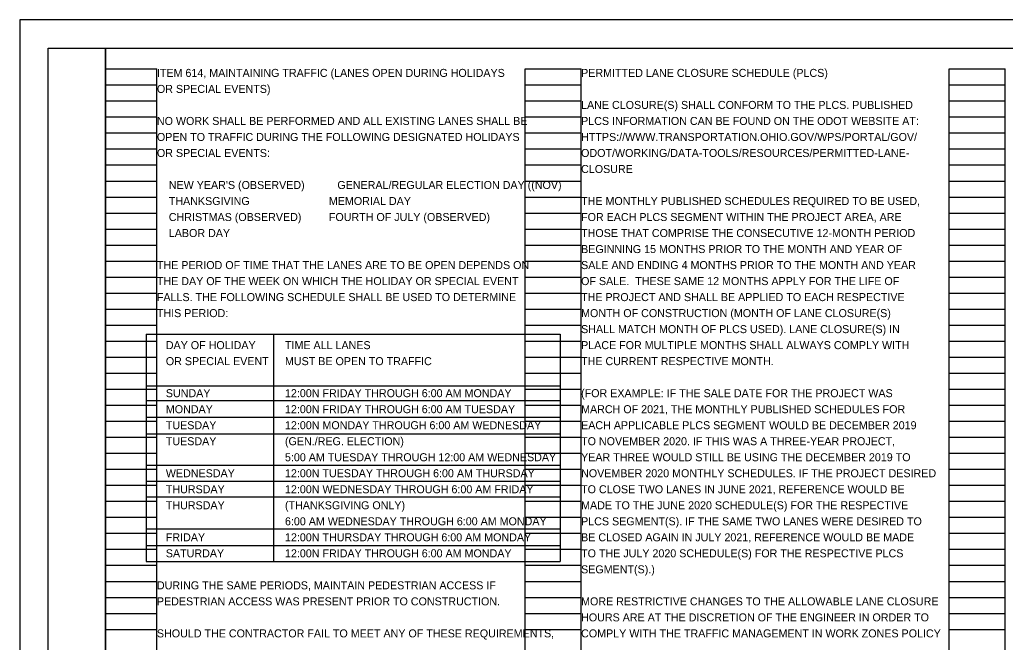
# Model space of a CAD drawing. Extents: x 0 to 49.3, y -31.9 to 22.
# Drawn here: x 0 to 17.24, y 11.11 to 22 of the extents above; entities that cross this region are included whole.
import ezdxf

# ---------------------------------------------------------------- set-up
doc = ezdxf.new("R2010")
doc.units = 0
for name, color, linetype in [('SH_Border', 7, 'Continuous'), ('SH_Cut_Line', 7, 'Continuous'), ('SH_Data', 7, 'Continuous'), ('SH_Text', 7, 'Continuous')]:
    doc.layers.add(name, color=color, linetype=linetype)

msp = doc.modelspace()

# ---------------------------------------------------------------- linework, layer by layer
at = {"layer": 'SH_Border'}
for points in [[(0.5, 21.5), (1.5, 21.5), (1.5, 0.5), (0.5, 0.5)], [(1.5, 21.5), (33.5, 21.5), (33.5, 0.5), (1.5, 0.5)]]:
    msp.add_lwpolyline(points, close=True, dxfattribs=at)
at = {"layer": 'SH_Cut_Line'}
msp.add_lwpolyline([(0, 0), (34, 0), (34, 22), (0, 22)], close=True, dxfattribs=at)
at = {"layer": 'SH_Data'}
for p, q in [((1.5, 0.98), (1.5, 21.14)), ((1.5, 21.14), (2.4, 21.14)), ((2.4, 0.98), (2.4, 21.14)), ((8.84, 0.98), (8.84, 21.14)), ((8.84, 21.14), (9.82, 21.14)), ((9.82, 0.98), (9.82, 21.14)), ((16.26, 0.98), (16.26, 21.14)), ((16.26, 21.14), (17.24, 21.14)), ((17.24, 0.98), (17.24, 21.14)), ((1.5, 20.86), (2.4, 20.86)), ((8.84, 20.86), (9.82, 20.86)), ((16.26, 20.86), (17.24, 20.86)), ((1.5, 20.58), (2.4, 20.58)), ((8.84, 20.58), (9.82, 20.58)), ((16.26, 20.58), (17.24, 20.58)), ((1.5, 20.3), (2.4, 20.3)), ((8.84, 20.3), (9.82, 20.3)), ((16.26, 20.3), (17.24, 20.3)), ((1.5, 20.02), (2.4, 20.02)), ((8.84, 20.02), (9.82, 20.02)), ((16.26, 20.02), (17.24, 20.02)), ((1.5, 19.74), (2.4, 19.74)), ((8.84, 19.74), (9.82, 19.74)), ((16.26, 19.74), (17.24, 19.74)), ((1.5, 19.46), (2.4, 19.46)), ((8.84, 19.46), (9.82, 19.46)), ((16.26, 19.46), (17.24, 19.46)), ((1.5, 19.18), (2.4, 19.18)), ((8.84, 19.18), (9.82, 19.18)), ((16.26, 19.18), (17.24, 19.18)), ((1.5, 18.9), (2.4, 18.9)), ((8.84, 18.9), (9.82, 18.9)), ((16.26, 18.9), (17.24, 18.9)), ((1.5, 18.62), (2.4, 18.62)), ((8.84, 18.62), (9.82, 18.62)), ((16.26, 18.62), (17.24, 18.62)), ((1.5, 18.34), (2.4, 18.34)), ((8.84, 18.34), (9.82, 18.34)), ((16.26, 18.34), (17.24, 18.34)), ((1.5, 18.06), (2.4, 18.06)), ((8.84, 18.06), (9.82, 18.06)), ((16.26, 18.06), (17.24, 18.06)), ((1.5, 17.78), (2.4, 17.78)), ((8.84, 17.78), (9.82, 17.78)), ((16.26, 17.78), (17.24, 17.78)), ((1.5, 17.5), (2.4, 17.5)), ((8.84, 17.5), (9.82, 17.5)), ((16.26, 17.5), (17.24, 17.5)), ((1.5, 17.22), (2.4, 17.22)), ((8.84, 17.22), (9.82, 17.22)), ((16.26, 17.22), (17.24, 17.22)), ((1.5, 16.94), (2.4, 16.94)), ((8.84, 16.94), (9.82, 16.94)), ((16.26, 16.94), (17.24, 16.94)), ((1.5, 16.66), (2.4, 16.66)), ((8.84, 16.66), (9.82, 16.66)), ((16.26, 16.66), (17.24, 16.66)), ((1.5, 16.38), (2.4, 16.38)), ((8.84, 16.38), (9.82, 16.38)), ((16.26, 16.38), (17.24, 16.38)), ((1.5, 16.1), (2.4, 16.1)), ((8.84, 16.1), (9.82, 16.1)), ((16.26, 16.1), (17.24, 16.1)), ((1.5, 15.82), (2.4, 15.82)), ((8.84, 15.82), (9.82, 15.82)), ((16.26, 15.82), (17.24, 15.82)), ((1.5, 15.54), (2.4, 15.54)), ((8.84, 15.54), (9.82, 15.54)), ((16.26, 15.54), (17.24, 15.54)), ((1.5, 15.26), (2.4, 15.26)), ((8.84, 15.26), (9.82, 15.26)), ((16.26, 15.26), (17.24, 15.26)), ((1.5, 14.98), (2.4, 14.98)), ((8.84, 14.98), (9.82, 14.98)), ((16.26, 14.98), (17.24, 14.98)), ((1.5, 14.7), (2.4, 14.7)), ((8.84, 14.7), (9.82, 14.7)), ((16.26, 14.7), (17.24, 14.7)), ((1.5, 14.42), (2.4, 14.42)), ((8.84, 14.42), (9.82, 14.42)), ((16.26, 14.42), (17.24, 14.42)), ((1.5, 14.14), (2.4, 14.14)), ((8.84, 14.14), (9.82, 14.14)), ((16.26, 14.14), (17.24, 14.14)), ((1.5, 13.86), (2.4, 13.86)), ((8.84, 13.86), (9.82, 13.86)), ((16.26, 13.86), (17.24, 13.86)), ((1.5, 13.58), (2.4, 13.58)), ((8.84, 13.58), (9.82, 13.58)), ((16.26, 13.58), (17.24, 13.58)), ((1.5, 13.3), (2.4, 13.3)), ((8.84, 13.3), (9.82, 13.3)), ((16.26, 13.3), (17.24, 13.3)), ((1.5, 13.02), (2.4, 13.02)), ((8.84, 13.02), (9.82, 13.02)), ((16.26, 13.02), (17.24, 13.02)), ((1.5, 12.74), (2.4, 12.74)), ((8.84, 12.74), (9.82, 12.74)), ((16.26, 12.74), (17.24, 12.74)), ((1.5, 12.46), (2.4, 12.46)), ((8.84, 12.46), (9.82, 12.46)), ((16.26, 12.46), (17.24, 12.46)), ((1.5, 12.18), (2.4, 12.18)), ((8.84, 12.18), (9.82, 12.18)), ((16.26, 12.18), (17.24, 12.18)), ((1.5, 11.9), (2.4, 11.9)), ((8.84, 11.9), (9.82, 11.9)), ((16.26, 11.9), (17.24, 11.9)), ((1.5, 11.62), (2.4, 11.62)), ((8.84, 11.62), (9.82, 11.62)), ((16.26, 11.62), (17.24, 11.62)), ((1.5, 11.34), (2.4, 11.34)), ((8.84, 11.34), (9.82, 11.34)), ((16.26, 11.34), (17.24, 11.34))]:
    msp.add_line(p, q, dxfattribs=at)
at = {"layer": 'SH_Text'}
for p, q in [((2.212, 16.5), (2.212, 12.527)), ((2.212, 16.5), (9.454, 16.5)), ((4.439, 16.5), (4.439, 12.527)), ((9.454, 16.5), (9.454, 12.527)), ((2.212, 15.597), (9.454, 15.597)), ((2.212, 15.343), (9.454, 15.343)), ((2.212, 15.052), (9.454, 15.052)), ((2.212, 14.761), (9.454, 14.761)), ((2.212, 14.21), (9.454, 14.21)), ((2.212, 13.934), (9.454, 13.934)), ((2.212, 13.658), (9.454, 13.658)), ((2.212, 13.099), (9.454, 13.099)), ((2.212, 12.808), (9.454, 12.808)), ((2.212, 12.527), (9.454, 12.527))]:
    msp.add_line(p, q, dxfattribs=at)

# ---------------------------------------------------------------- texts
for s, p in [('ITEM 614, MAINTAINING TRAFFIC (LANES OPEN DURING HOLIDAYS', (2.4, 21)), ('PERMITTED LANE CLOSURE SCHEDULE (PLCS)', (9.82, 21)), ('OR SPECIAL EVENTS)', (2.4, 20.72)), ('LANE CLOSURE(S) SHALL CONFORM TO THE PLCS. PUBLISHED', (9.82, 20.44)), ('NO WORK SHALL BE PERFORMED AND ALL EXISTING LANES SHALL BE', (2.4, 20.16)), ('PLCS INFORMATION CAN BE FOUND ON THE ODOT WEBSITE AT:', (9.82, 20.16)), ('OPEN TO TRAFFIC DURING THE FOLLOWING DESIGNATED HOLIDAYS', (2.4, 19.88)), ('HTTPS://WWW.TRANSPORTATION.OHIO.GOV/WPS/PORTAL/GOV/', (9.82, 19.88)), ('OR SPECIAL EVENTS:', (2.4, 19.6)), ('ODOT/WORKING/DATA-TOOLS/RESOURCES/PERMITTED-LANE-', (9.82, 19.6)), ('CLOSURE', (9.82, 19.32)), ("    NEW YEAR'S (OBSERVED)           GENERAL/REGULAR ELECTION DAY ((NOV)", (2.4, 19.04)), ('    THANKSGIVING', (2.4, 18.76)), ('    MEMORIAL DAY                   ', (5.2, 18.76)), ('THE MONTHLY PUBLISHED SCHEDULES REQUIRED TO BE USED,', (9.82, 18.76)), ('    CHRISTMAS (OBSERVED)', (2.4, 18.48)), ('    FOURTH OF JULY (OBSERVED)      ', (5.2, 18.48)), ('FOR EACH PLCS SEGMENT WITHIN THE PROJECT AREA, ARE', (9.82, 18.48)), ('    LABOR DAY', (2.4, 18.2)), ('THOSE THAT COMPRISE THE CONSECUTIVE 12-MONTH PERIOD', (9.82, 18.2)), ('BEGINNING 15 MONTHS PRIOR TO THE MONTH AND YEAR OF ', (9.82, 17.92)), ('THE PERIOD OF TIME THAT THE LANES ARE TO BE OPEN DEPENDS ON', (2.4, 17.64)), ('SALE AND ENDING 4 MONTHS PRIOR TO THE MONTH AND YEAR', (9.82, 17.64)), ('THE DAY OF THE WEEK ON WHICH THE HOLIDAY OR SPECIAL EVENT', (2.4, 17.36)), ('OF SALE.  THESE SAME 12 MONTHS APPLY FOR THE LIFE OF', (9.82, 17.36)), ('FALLS. THE FOLLOWING SCHEDULE SHALL BE USED TO DETERMINE', (2.4, 17.08)), ('THE PROJECT AND SHALL BE APPLIED TO EACH RESPECTIVE', (9.82, 17.08)), ('THIS PERIOD:', (2.4, 16.8)), ('MONTH OF CONSTRUCTION (MONTH OF LANE CLOSURE(S)', (9.82, 16.8)), ('SHALL MATCH MONTH OF PLCS USED). LANE CLOSURE(S) IN', (9.82, 16.52)), ('   DAY OF HOLIDAY        ', (2.4, 16.24)), ('TIME ALL LANES', (4.64, 16.24)), ('PLACE FOR MULTIPLE MONTHS SHALL ALWAYS COMPLY WITH', (9.82, 16.24)), ('   OR SPECIAL EVENT   ', (2.4, 15.96)), ('MUST BE OPEN TO TRAFFIC', (4.64, 15.96)), ('THE CURRENT RESPECTIVE MONTH. ', (9.82, 15.96)), ('   SUNDAY     ', (2.4, 15.4)), ('12:00N FRIDAY THROUGH 6:00 AM MONDAY', (4.64, 15.4)), ('(FOR EXAMPLE: IF THE SALE DATE FOR THE PROJECT WAS', (9.82, 15.4)), ('   MONDAY     ', (2.4, 15.12)), ('12:00N FRIDAY THROUGH 6:00 AM TUESDAY', (4.64, 15.12)), ('MARCH OF 2021, THE MONTHLY PUBLISHED SCHEDULES FOR', (9.82, 15.12)), ('   TUESDAY    ', (2.4, 14.84)), ('12:00N MONDAY THROUGH 6:00 AM WEDNESDAY', (4.64, 14.84)), ('EACH APPLICABLE PLCS SEGMENT WOULD BE DECEMBER 2019', (9.82, 14.84)), ('   TUESDAY    ', (2.4, 14.56)), ('(GEN./REG. ELECTION)', (4.64, 14.56)), ('TO NOVEMBER 2020. IF THIS WAS A THREE-YEAR PROJECT,', (9.82, 14.56)), ('5:00 AM TUESDAY THROUGH 12:00 AM WEDNESDAY', (4.64, 14.28)), ('YEAR THREE WOULD STILL BE USING THE DECEMBER 2019 TO', (9.82, 14.28)), ('   WEDNESDAY  ', (2.4, 14)), ('12:00N TUESDAY THROUGH 6:00 AM THURSDAY', (4.64, 14)), ('NOVEMBER 2020 MONTHLY SCHEDULES. IF THE PROJECT DESIRED', (9.82, 14)), ('   THURSDAY   ', (2.4, 13.72)), ('12:00N WEDNESDAY THROUGH 6:00 AM FRIDAY', (4.64, 13.72)), ('TO CLOSE TWO LANES IN JUNE 2021, REFERENCE WOULD BE', (9.82, 13.72)), ('   THURSDAY   ', (2.4, 13.44)), ('(THANKSGIVING ONLY)', (4.64, 13.44)), ('MADE TO THE JUNE 2020 SCHEDULE(S) FOR THE RESPECTIVE', (9.82, 13.44)), ('6:00 AM WEDNESDAY THROUGH 6:00 AM MONDAY', (4.64, 13.16)), ('PLCS SEGMENT(S). IF THE SAME TWO LANES WERE DESIRED TO', (9.82, 13.16)), ('   FRIDAY     ', (2.4, 12.88)), ('12:00N THURSDAY THROUGH 6:00 AM MONDAY', (4.64, 12.88)), ('BE CLOSED AGAIN IN JULY 2021, REFERENCE WOULD BE MADE', (9.82, 12.88)), ('   SATURDAY   ', (2.4, 12.6)), ('12:00N FRIDAY THROUGH 6:00 AM MONDAY', (4.64, 12.6)), ('TO THE JULY 2020 SCHEDULE(S) FOR THE RESPECTIVE PLCS', (9.82, 12.6)), ('SEGMENT(S).)', (9.82, 12.32)), ('DURING THE SAME PERIODS, MAINTAIN PEDESTRIAN ACCESS IF', (2.4, 12.04)), ('PEDESTRIAN ACCESS WAS PRESENT PRIOR TO CONSTRUCTION.', (2.4, 11.76)), ('MORE RESTRICTIVE CHANGES TO THE ALLOWABLE LANE CLOSURE', (9.82, 11.76)), ('HOURS ARE AT THE DISCRETION OF THE ENGINEER IN ORDER TO', (9.82, 11.48)), ('SHOULD THE CONTRACTOR FAIL TO MEET ANY OF THESE REQUIREMENTS,', (2.4, 11.2)), ('COMPLY WITH THE TRAFFIC MANAGEMENT IN WORK ZONES POLICY', (9.82, 11.2))]:
    msp.add_text(s, height=0.14, dxfattribs=at).set_placement(p)

doc.saveas('drawing.dxf')
